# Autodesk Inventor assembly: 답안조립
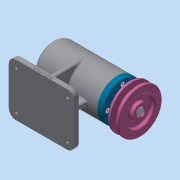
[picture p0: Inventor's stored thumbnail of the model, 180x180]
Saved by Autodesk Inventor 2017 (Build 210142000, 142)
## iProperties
Part Number: 답안조립
Material: 일반
Document SubType Name: Assembly
Designer: mrc
Author: mrc
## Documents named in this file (12)
- C:\Users\mrc\Desktop\701004V1024\답안조립.iam
- C:\Users\mrc\Desktop\701004V1024\본체.ipt
- C:\Users\mrc\Desktop\701004V1024\V벨트풀리.ipt
- C:\Users\mrc\Desktop\701004V1024\멈춤나사 M3.ipt
- C:\Users\mrc\Desktop\701004V1024\베어링 6004.ipt
- C:\Users\mrc\Desktop\701004V1024\베어링 51202.ipt
- C:\Users\mrc\Desktop\701004V1024\볼트 M4.ipt
- C:\Users\mrc\Desktop\701004V1024\어댑터슬리브.ipt
- C:\Users\mrc\Desktop\701004V1024\오일 실.ipt
- C:\Users\mrc\Desktop\701004V1024\축.ipt
- C:\Users\mrc\Desktop\701004V1024\커버.ipt
- C:\Users\mrc\Desktop\701004V1024\키 5 x 5 x 16.ipt
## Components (1 placed, 1 different names)
1. V벨트풀리:1
